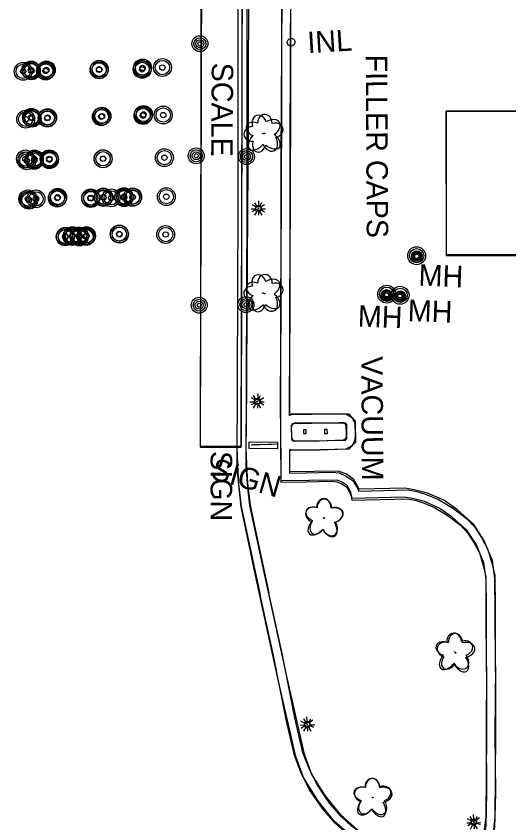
# Model space of a CAD drawing. Extents: x 588843 to 2552415, y 180129 to 269402.
# Drawn here: x 594348.8 to 594486.6, y 184634.7 to 184860.3 of the extents above; entities that cross this region are included whole.
import ezdxf

# ---------------------------------------------------------------- set-up
doc = ezdxf.new("R2010")
doc.units = 0
for name, color, linetype in [('Default', 7, 'Continuous'), ('E_AREA', 7, 'Continuous'), ('E_BLD_Dash', 7, 'Continuous'), ('E_BLD_HvyDash', 7, 'Continuous'), ('E_BLD_Text', 7, 'Continuous'), ('E_BLD_Vacuum', 7, 'Continuous'), ('E_DRN', 7, 'Continuous'), ('E_DRN_Text', 7, 'Continuous'), ('E_DWY', 7, 'Continuous'), ('E_LAND_Vegetation', 7, 'Continuous'), ('E_LTG', 7, 'Continuous'), ('E_MISCPROP', 7, 'Continuous'), ('E_MISCPROP_Text', 7, 'Continuous'), ('E_SGN', 7, 'Continuous'), ('E_SGN_Text', 7, 'Continuous'), ('E_UTL_MH', 7, 'Continuous'), ('E_UTL_MH_Text', 7, 'Continuous')]:
    doc.layers.add(name, color=color, linetype=linetype)

# ---------------------------------------------------------------- blocks, each defined once
blk = doc.blocks.new('SIGN')
at = {"layer": 'Default'}
blk.add_text('SIGN', height=12, dxfattribs=at).set_placement((-18.55, -6))
blk = doc.blocks.new('SCAL')
at = {"layer": 'Default'}
blk.add_text('SCALE', height=12, dxfattribs=at).set_placement((-23.24, -6))
blk = doc.blocks.new('POLE')
at = {"layer": 'Default'}
for radius in [4.46, 3.35, 2.23, 1.12]:
    blk.add_circle((0, 0), radius, dxfattribs=at)
blk = doc.blocks.new('LPOL')
at = {"layer": 'Default'}
for p, q in [((-4, 0), (-1.5, 0)), ((-0.75, 1.3), (-2, 3.46)), ((0.75, 1.3), (2, 3.46)), ((1.5, 0), (4, 0)), ((-2, -3.46), (-0.75, -1.3)), ((2, -3.46), (0.75, -1.3))]:
    blk.add_line(p, q, dxfattribs=at)
for radius in [1.5, 1.5, 1.5, 0.125]:
    blk.add_circle((0, 0), radius, dxfattribs=at)
blk = doc.blocks.new('DTRE')
at = {"layer": 'Default'}
blk.add_circle((-0.18, 0), 0.183, dxfattribs=at)
for centre, major_axis, ratio in [((-1.87, 5.32), (1.36, -4.98), 0.782863), ((4.06, 2.74), (-5.27, -2.93), 0.691916), ((-5.87, 0.15), (4.93, -0.12), 0.832022), ((-2.49, -5.24), (1.8, 4.86), 0.716896), ((3.54, -3.71), (-5.01, 4.58), 0.560249)]:
    blk.add_ellipse(centre, major_axis=major_axis, ratio=ratio, start_param=1.570796, end_param=4.712389, dxfattribs=at)
blk = doc.blocks.new('FILO')
at = {"layer": 'E_MISCPROP'}
for radius in [5, 4, 1.5]:
    blk.add_circle((0, 0), radius, dxfattribs=at)
blk = doc.blocks.new('VACO')
at = {"layer": 'E_BLD_Vacuum'}
blk.add_lwpolyline([(0, 1.5), (0, 0), (2.2, 0), (2.2, 1.5), (0, 1.5)], close=True, dxfattribs=at)
blk = doc.blocks.new('VAC')
at = {"layer": 'E_BLD_Text'}
blk.add_text('VACUUM', height=12, dxfattribs=at).set_placement((-33.33, -6))
blk = doc.blocks.new('FILT_4')
at = {"layer": 'E_MISCPROP_Text'}
blk.add_text('FILLER CAPS', height=12, dxfattribs=at).set_placement((10, -6))
blk = doc.blocks.new('LPOL_4')
at = {"layer": 'E_LTG'}
for p, q in [((-13.1, 0), (-4.9, 0)), ((-2.5, 4.3), (-6.6, 11.4)), ((2.5, 4.3), (6.6, 11.4)), ((4.9, 0), (13.1, 0)), ((-6.6, -11.4), (-2.5, -4.3)), ((6.6, -11.4), (2.5, -4.3))]:
    blk.add_line(p, q, dxfattribs=at)
for radius in [4.92, 4.92, 4.92, 0.41]:
    blk.add_circle((0, 0), radius, dxfattribs=at)
blk = doc.blocks.new('FILO_1')
at = {"layer": 'E_MISCPROP'}
for radius in [16.4, 13.1, 4.92]:
    blk.add_circle((0, 0), radius, dxfattribs=at)
blk = doc.blocks.new('INLT_32_2')
at = {"layer": 'E_DRN_Text'}
blk.add_text('INL', height=39.37, dxfattribs=at).set_placement((-36.2, -19.7))
blk = doc.blocks.new('MHO_3')
at = {"layer": 'E_UTL_MH'}
for centre, radius in [((0.3, -0.4), 9.84), ((0.3, -0.4), 7.98), ((0.2, -0.5), 6.35), ((0.1, -0.5), 3.97)]:
    blk.add_circle(centre, radius, dxfattribs=at)
blk = doc.blocks.new('MHT_3')
at = {"layer": 'E_UTL_MH_Text'}
blk.add_text('MH', height=39.37, dxfattribs=at).set_placement((-32.2, -19.7))
blk = doc.blocks.new('DTRE_4')
at = {"layer": 'E_LAND_Vegetation'}
blk.add_circle((-0.6, 0), 0.601, dxfattribs=at)
for centre, major_axis, ratio in [((-6.1, 17.5), (4.5, -16.3), 0.782863), ((13.3, 9), (-17.3, -9.6), 0.691916), ((-19.3, 0.5), (16.2, -0.4), 0.832022), ((-8.2, -17.2), (5.9, 15.9), 0.716896), ((11.6, -12.2), (-16.4, 15), 0.560249)]:
    blk.add_ellipse(centre, major_axis=major_axis, ratio=ratio, start_param=1.570796, end_param=4.712389, dxfattribs=at)
blk = doc.blocks.new('SIGN_3')
at = {"layer": 'E_SGN'}
blk.add_text('SIGN', height=39.37, dxfattribs=at).set_placement((-56.1, -19.7))

msp = doc.modelspace()

# ---------------------------------------------------------------- linework, layer by layer
at = {"layer": 'E_AREA'}
msp.add_lwpolyline([(594414.04, 184741.25), (594421.91, 184741.15), (594421.89, 184739.31), (594414.02, 184739.41)], close=True, dxfattribs=at)
at = {"layer": 'E_BLD_Dash'}
msp.add_lwpolyline([(594400.82, 184942.87), (594400.29, 184739.8), (594411.76, 184739.77), (594412.3, 184942.83)], close=True, dxfattribs=at)
at = {"layer": 'E_BLD_HvyDash'}
for points in [[(594412.17, 184942.93), (594411.81, 184740.07), (594400.36, 184739.94), (594400.8, 184943.06), (594412.17, 184942.93)], [(594469.12, 184833.63), (594539.86, 184833.96), (594539.49, 184793.32), (594469.23, 184793.25)], [(594469.2, 184793.54), (594469.17, 184833.83), (594540.12, 184833.88), (594540.15, 184793.6), (594469.2, 184793.54)]]:
    msp.add_lwpolyline(points, close=True, dxfattribs=at)
at = {"layer": 'E_DRN'}
msp.add_ellipse((594425.73, 184853.02), major_axis=(0.31, 1.04), ratio=0.999083, dxfattribs=at)
at = {"layer": 'E_DWY'}
for points in [[(594421.96, 184675.59), (594415.82, 184703.87), (594411.73, 184723.08), (594411.26, 184727.36), (594410.68, 184734.11), (594410.96, 184807.45), (594410.92, 184870.64), (594411.16, 184901.91), (594411.17, 184939.88)], [(594424.41, 184676.12), (594418.27, 184704.4), (594414.2, 184723.48), (594413.75, 184727.6), (594413.18, 184734.21), (594413.46, 184807.45), (594413.42, 184870.63), (594413.66, 184901.89), (594413.67, 184939.88)], [(594447.77, 184915.17), (594448.18, 184897.65), (594448.19, 184895.9), (594447.53, 184894.66), (594446.24, 184893.39), (594445.15, 184892.78), (594441.01, 184892.63), (594423.19, 184892.62), (594423.1, 184870.83), (594423.02, 184855.19), (594423.02, 184838.7), (594422.95, 184807.7), (594422.8, 184779.99), (594422.79, 184749.18), (594422.83, 184730.02), (594429.93, 184730.14)], [(594450.27, 184915.23), (594450.68, 184897.69), (594450.7, 184895.29), (594449.56, 184893.15), (594447.76, 184891.37), (594445.84, 184890.3), (594441.06, 184890.13), (594425.68, 184890.12), (594425.6, 184870.82), (594425.52, 184855.18), (594425.52, 184838.7), (594425.45, 184807.69), (594425.3, 184779.99), (594425.29, 184749.18), (594425.29, 184748.72)], [(594425.33, 184748.66), (594425.31, 184753.72), (594425.45, 184777.31), (594425.48, 184799.41), (594425.47, 184820.54), (594425.6, 184851.34), (594425.7, 184865.36), (594425.84, 184889.86), (594440.33, 184889.96), (594445.07, 184890.02), (594447.12, 184890.68), (594448.91, 184892.09), (594450.28, 184894.21), (594450.81, 184896.05), (594450.4, 184915.27)], [(594413.61, 184904.03), (594413.83, 184876.2), (594413.68, 184831.02), (594413.36, 184779.01), (594413.27, 184758.12), (594413.16, 184745.67)], [(594480.38, 184678.45), (594480.29, 184693.97), (594480.25, 184702.88), (594479.6, 184707.44), (594477.45, 184712.65), (594474.89, 184716.54), (594470.69, 184720.3), (594467.18, 184722.78), (594463.03, 184724.57), (594459.67, 184725.43), (594457.35, 184725.79), (594442.77, 184725.45), (594442.43, 184727.18), (594441.4, 184729.04), (594440.03, 184730.04), (594438.57, 184730.59), (594422.92, 184730.39), (594422.81, 184753.72), (594422.95, 184777.32), (594422.98, 184799.41), (594422.97, 184820.54), (594423.1, 184851.35), (594423.2, 184865.37)], [(594425.29, 184748.72), (594425.71, 184748.95), (594428.09, 184749), (594431.39, 184749)], [(594425.33, 184748.66), (594426.05, 184749.18), (594430.53, 184749.13)], [(594430.53, 184749.13), (594441.92, 184749.14), (594443.68, 184747.16), (594443.72, 184741.05), (594441.92, 184739.2), (594425.72, 184738.9), (594425.38, 184739.21)], [(594431.39, 184749), (594439.19, 184749.23), (594441.02, 184749.14), (594442.61, 184748.22), (594443.51, 184746.61), (594443.62, 184742.75), (594443.43, 184741.59), (594442.76, 184740.19), (594441.05, 184739.24), (594433.7, 184738.99)], [(594413.16, 184745.76), (594413.06, 184739.72), (594413.22, 184735), (594413.55, 184729.65), (594414.24, 184723.57), (594416.79, 184711.65), (594419.51, 184699.02)], [(594433.61, 184741.49), (594426.99, 184741.49), (594426.31, 184741.49), (594426.03, 184741.7), (594425.87, 184745.13), (594425.92, 184745.79), (594425.99, 184746.04), (594426.06, 184746.29), (594426.38, 184746.47), (594428.15, 184746.5), (594431.47, 184746.5)], [(594430.51, 184746.63), (594440.81, 184746.62), (594441.19, 184746.2), (594441.21, 184742.06), (594440.85, 184741.68), (594426.66, 184741.42), (594425.97, 184742.03), (594425.89, 184745.98), (594426.85, 184746.67), (594430.51, 184746.63)], [(594431.46, 184746.5), (594439.16, 184746.73), (594440.3, 184746.67), (594440.76, 184746.41), (594441.03, 184745.92), (594441.12, 184742.93), (594441.02, 184742.35), (594440.85, 184741.99), (594440.37, 184741.72), (594433.61, 184741.49)], [(594410.57, 184740.06), (594410.56, 184739.73), (594410.72, 184734.88), (594411.06, 184729.43), (594411.77, 184723.16), (594414.34, 184711.12), (594417.07, 184698.49)], [(594433.61, 184738.99), (594427, 184738.99), (594425.47, 184738.97), (594425.31, 184739.1)], [(594425.31, 184739.1), (594425.33, 184732.56), (594429.89, 184732.64)], [(594482.88, 184678.47), (594482.79, 184693.99), (594482.75, 184703.06), (594482.03, 184708.1), (594479.67, 184713.83), (594476.79, 184718.19), (594472.24, 184722.26), (594468.4, 184724.97), (594463.84, 184726.94), (594460.17, 184727.88), (594457.52, 184728.3), (594444.82, 184728), (594444.81, 184728.05), (594443.31, 184730.74), (594441.24, 184732.25), (594439.02, 184733.09), (594425.41, 184732.92), (594425.38, 184739.21)], [(594429.89, 184732.64), (594437.11, 184732.76), (594439.18, 184732.59), (594440.91, 184731.79), (594443.01, 184730.46), (594444.33, 184728.29), (594444.65, 184727.5), (594458.45, 184727.82), (594460.86, 184727.37), (594463.28, 184726.67), (594466.98, 184725.17), (594471.11, 184722.67), (594474.83, 184719.84), (594477.08, 184717.42), (594479.04, 184714.38), (594480.73, 184711.16), (594481.84, 184707.32), (594482.71, 184704), (594482.83, 184694.45)], [(594429.93, 184730.14), (594437.03, 184730.25), (594438.53, 184730.13), (594439.71, 184729.59), (594441.18, 184728.66), (594442.09, 184727.17), (594442.51, 184726.13), (594442.68, 184724.95), (594458.25, 184725.31), (594460.29, 184724.93), (594462.46, 184724.31), (594465.86, 184722.93), (594469.7, 184720.6), (594473.14, 184717.97), (594475.1, 184715.88), (594476.87, 184713.12), (594478.4, 184710.22), (594479.43, 184706.65), (594480.21, 184703.67), (594480.33, 184694.42)], [(594420.77, 184681.55), (594417.07, 184698.49)], [(594423.21, 184682.07), (594419.51, 184699.02)], [(594482.83, 184694.42), (594482.92, 184659.67), (594482.71, 184636.24), (594482.31, 184632.89), (594481.78, 184630.62), (594480.58, 184627.84), (594478.42, 184625.82), (594475.9, 184623.95), (594473.46, 184623.13), (594469.07, 184622.62), (594458.61, 184624.11), (594452.88, 184625.43), (594448.95, 184627.22), (594443.75, 184630.02), (594437.8, 184635.22), (594433.19, 184640.96), (594429.19, 184647.4), (594427.04, 184653.28), (594421.97, 184675.56)], [(594480.33, 184694.42), (594480.42, 184659.68), (594480.21, 184636.4), (594479.84, 184633.33), (594479.39, 184631.41), (594478.49, 184629.31), (594476.81, 184627.74), (594474.73, 184626.19), (594472.92, 184625.58), (594469.1, 184625.14), (594459.07, 184626.57), (594453.69, 184627.81), (594450.06, 184629.46), (594445.18, 184632.08), (594439.62, 184636.95), (594435.24, 184642.4), (594431.45, 184648.5), (594429.44, 184654), (594424.41, 184676.12)], [(594482.88, 184678.47), (594482.74, 184659.75), (594482.91, 184643.05), (594482.66, 184633.41), (594481.76, 184629.69), (594479.69, 184626.74), (594476.79, 184624.45), (594474.31, 184623.27), (594471.26, 184622.72), (594468.48, 184622.7), (594461.92, 184623.38), (594457.38, 184624.13), (594453.05, 184625.41), (594448.66, 184627.01), (594444.67, 184629.31), (594440.93, 184632.02), (594438.05, 184634.69), (594434.53, 184638.75), (594430.91, 184644.03), (594428.65, 184648.48), (594426.64, 184653.58), (594424.31, 184663.61), (594420.77, 184681.55)], [(594480.38, 184678.45), (594480.24, 184659.73), (594480.41, 184643.07), (594480.16, 184633.74), (594479.44, 184630.73), (594477.86, 184628.48), (594475.46, 184626.59), (594473.53, 184625.67), (594471.03, 184625.21), (594468.6, 184625.2), (594462.25, 184625.86), (594457.94, 184626.57), (594453.83, 184627.78), (594449.72, 184629.28), (594446.03, 184631.41), (594442.52, 184633.96), (594439.84, 184636.43), (594436.51, 184640.28), (594433.07, 184645.31), (594430.94, 184649.51), (594429.04, 184654.33), (594426.75, 184664.14), (594423.21, 184682.07)]]:
    msp.add_lwpolyline(points, dxfattribs=at)
at = {"layer": 'E_SGN'}
msp.add_line((594421.87, 184740.65), (594414.62, 184740.37), dxfattribs=at)
msp.add_lwpolyline([(594414.75, 184740.55), (594420.13, 184740.61)], dxfattribs=at)

# ---------------------------------------------------------------- block references
at = {"layer": 'E_BLD_Text'}
for name, p, xscale, yscale, rotation in [('SCAL', (594406.47, 184835.67), 0.4999999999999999, 0.49999999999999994, -90.39935623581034), ('VAC', (594448.43, 184748.55), 0.49999999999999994, 0.4999999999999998, -89.6710262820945)]:
    msp.add_blockref(name, p, dxfattribs=dict(at, xscale=xscale, yscale=yscale, rotation=rotation))
at = {"layer": 'E_BLD_Vacuum', "xscale": 0.49999999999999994, "yscale": 0.4999999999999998, "rotation": -89.6710262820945}
for p in [(594429.23, 184744.67), (594435.11, 184744.74)]:
    msp.add_blockref('VACO', p, dxfattribs=at)
at = {"layer": 'E_DRN_Text', "xscale": 0.15240030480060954, "yscale": 0.15240030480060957, "rotation": 3.4338469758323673}
msp.add_blockref('INLT_32_2', (594435.79, 184853.25), dxfattribs=at)
at = {"layer": 'E_LAND_Vegetation'}
for name, p, xscale, yscale, rotation in [('DTRE_4', (594417.96, 184827.49), 0.15240030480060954, 0.15240030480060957, 3.4338469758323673), ('DTRE', (594418.29, 184827.42), 0.4999999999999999, 0.49999999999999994, -90.39935623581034), ('DTRE_4', (594417.89, 184782.87), 0.15240030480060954, 0.15240030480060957, 3.4338469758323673), ('DTRE', (594418.3, 184782.66), 0.4999999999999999, 0.49999999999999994, -90.39935623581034), ('DTRE_4', (594435.02, 184720.04), 0.1524003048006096, 0.1524003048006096, -15.969778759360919), ('DTRE', (594434.97, 184719.84), 0.49999999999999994, 0.4999999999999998, -89.6710262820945), ('DTRE_4', (594471.83, 184682.27), 0.1524003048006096, 0.1524003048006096, -15.969778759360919), ('DTRE', (594471.47, 184682.43), 0.49999999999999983, 0.4999999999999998, -85.64095942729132), ('DTRE_4', (594448.67, 184641.79), 0.1524003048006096, 0.1524003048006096, -15.969778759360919), ('DTRE', (594448.56, 184641.77), 0.49999999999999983, 0.4999999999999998, -85.64095942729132)]:
    msp.add_blockref(name, p, dxfattribs=dict(at, xscale=xscale, yscale=yscale, rotation=rotation))
at = {"layer": 'E_LTG'}
for name, p, xscale, yscale, rotation in [('LPOL_4', (594416.6, 184806.42), 0.15240030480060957, 0.15240030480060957, 0.8014450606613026), ('LPOL', (594416.6, 184806.63), 0.4999999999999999, 0.49999999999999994, -90.39935623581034), ('LPOL_4', (594416.22, 184752.47), 0.15240030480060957, 0.15240030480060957, 0.8014450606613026), ('LPOL', (594416.39, 184752.68), 0.4999999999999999, 0.49999999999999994, -90.39935623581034), ('LPOL_4', (594430.29, 184662.13), 0.15240030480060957, 0.15240030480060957, 0.8014450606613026), ('LPOL', (594430.2, 184662.38), 0.49999999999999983, 0.4999999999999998, -85.64095942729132), ('LPOL_4', (594476.84, 184634.78), 0.15240030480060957, 0.15240030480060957, 0.8014450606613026), ('LPOL', (594476.8, 184635.12), 0.49999999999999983, 0.4999999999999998, -85.64095942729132)]:
    msp.add_blockref(name, p, dxfattribs=dict(at, xscale=xscale, yscale=yscale, rotation=rotation))
at = {"layer": 'E_MISCPROP'}
for name, p, xscale, yscale, rotation in [('POLE', (594400.23, 184852.6), 0.4999999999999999, 0.49999999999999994, -90.39935623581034), ('FILO', (594384.19, 184845.81), 0.4999999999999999, 0.49999999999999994, -90.39935623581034), ('FILO', (594389.75, 184845.93), 0.4999999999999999, 0.49999999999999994, -90.39935623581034), ('FILO_1', (594350.81, 184844.86), 0.15240030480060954, 0.15240030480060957, 3.4338469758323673), ('FILO', (594352.96, 184845.22), 0.4999999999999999, 0.49999999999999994, -90.39935623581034), ('FILO_1', (594353.09, 184845.02), 0.15240030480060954, 0.15240030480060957, 3.4338469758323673), ('FILO_1', (594357.06, 184844.97), 0.15240030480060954, 0.15240030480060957, 3.4338469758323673), ('FILO', (594357.29, 184845.26), 0.4999999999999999, 0.49999999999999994, -90.39935623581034), ('FILO_1', (594372.02, 184845.28), 0.15240030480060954, 0.15240030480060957, 3.4338469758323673), ('FILO', (594372.1, 184845.45), 0.4999999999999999, 0.49999999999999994, -90.39935623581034), ('FILO_1', (594384.08, 184845.41), 0.15240030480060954, 0.15240030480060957, 3.4338469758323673), ('FILO_1', (594372.66, 184832.19), 0.15240030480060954, 0.15240030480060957, 3.4338469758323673), ('FILO', (594372.84, 184832.34), 0.4999999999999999, 0.49999999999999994, -90.39935623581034), ('FILO_1', (594384.31, 184832.51), 0.15240030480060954, 0.15240030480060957, 3.4338469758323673), ('FILO', (594384.45, 184832.81), 0.4999999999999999, 0.49999999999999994, -90.39935623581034), ('FILO', (594389.97, 184832.65), 0.4999999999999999, 0.49999999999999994, -90.39935623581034), ('FILO_1', (594351.51, 184831.48), 0.15240030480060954, 0.15240030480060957, 3.4338469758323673), ('FILO', (594353.12, 184831.99), 0.4999999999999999, 0.49999999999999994, -90.39935623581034), ('FILO_1', (594353.29, 184831.79), 0.15240030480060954, 0.15240030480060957, 3.4338469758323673), ('FILO_1', (594357.54, 184831.78), 0.15240030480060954, 0.15240030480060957, 3.4338469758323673), ('FILO', (594357.64, 184831.92), 0.4999999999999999, 0.49999999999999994, -90.39935623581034), ('POLE', (594399.19, 184821.24), 0.4999999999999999, 0.49999999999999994, -90.39935623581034), ('FILO', (594351.44, 184820.38), 0.4999999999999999, 0.49999999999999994, -90.39935623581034), ('FILO_1', (594351.83, 184819.84), 0.15240030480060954, 0.15240030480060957, 3.4338469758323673), ('FILO_1', (594353.9, 184819.99), 0.15240030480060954, 0.15240030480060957, 3.4338469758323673), ('FILO', (594353.94, 184820.37), 0.4999999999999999, 0.49999999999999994, -90.39935623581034), ('FILO_1', (594358.15, 184820.19), 0.15240030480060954, 0.15240030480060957, 3.4338469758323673), ('FILO', (594358.09, 184820.41), 0.4999999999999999, 0.49999999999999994, -90.39935623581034), ('FILO_1', (594373.15, 184820.43), 0.15240030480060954, 0.15240030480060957, 3.4338469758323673), ('FILO', (594373.16, 184820.41), 0.4999999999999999, 0.49999999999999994, -90.39935623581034), ('FILO', (594390.3, 184820.72), 0.4999999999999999, 0.49999999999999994, -90.39935623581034), ('POLE', (594413.26, 184821.02), 0.4999999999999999, 0.49999999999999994, -90.39935623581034), ('FILO', (594360.46, 184809.64), 0.4999999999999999, 0.49999999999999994, -90.39935623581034), ('FILO_1', (594373.22, 184809.59), 0.15240030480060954, 0.15240030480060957, 3.4338469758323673), ('FILO', (594373.25, 184809.72), 0.4999999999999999, 0.49999999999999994, -90.39935623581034), ('FILO_1', (594375.43, 184809.5), 0.15240030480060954, 0.15240030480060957, 3.4338469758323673), ('FILO_1', (594379.02, 184809.55), 0.15240030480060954, 0.15240030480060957, 3.4338469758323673), ('FILO', (594378.98, 184809.84), 0.4999999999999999, 0.49999999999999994, -90.39935623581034), ('FILO_1', (594381.34, 184809.63), 0.15240030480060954, 0.15240030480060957, 3.4338469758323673), ('FILO', (594381.44, 184809.75), 0.4999999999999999, 0.49999999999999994, -90.39935623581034), ('FILO', (594390.84, 184809.82), 0.4999999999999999, 0.49999999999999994, -90.39935623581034), ('FILO', (594352.11, 184809.19), 0.4999999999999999, 0.49999999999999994, -90.39935623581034), ('FILO_1', (594352.4, 184808.86), 0.15240030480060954, 0.15240030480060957, 3.4338469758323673), ('FILO', (594354.39, 184809.21), 0.4999999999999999, 0.49999999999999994, -90.39935623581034), ('FILO_1', (594360.34, 184809.43), 0.15240030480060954, 0.15240030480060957, 3.4338469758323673), ('FILO_1', (594369.7, 184809.32), 0.15240030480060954, 0.15240030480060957, 3.4338469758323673), ('FILO', (594369.68, 184809.49), 0.4999999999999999, 0.49999999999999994, -90.39935623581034), ('FILO_1', (594362.57, 184798.58), 0.15240030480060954, 0.15240030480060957, 3.4338469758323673), ('FILO', (594362.6, 184798.73), 0.4999999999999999, 0.49999999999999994, -90.39935623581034), ('FILO_1', (594364.5, 184798.71), 0.15240030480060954, 0.15240030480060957, 3.4338469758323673), ('FILO', (594364.65, 184798.91), 0.4999999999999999, 0.49999999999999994, -90.39935623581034), ('FILO_1', (594366.48, 184798.55), 0.15240030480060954, 0.15240030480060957, 3.4338469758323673), ('FILO', (594366.52, 184798.88), 0.4999999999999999, 0.49999999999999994, -90.39935623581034), ('FILO_1', (594368.35, 184798.69), 0.15240030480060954, 0.15240030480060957, 3.4338469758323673), ('FILO', (594368.51, 184798.9), 0.4999999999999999, 0.49999999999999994, -90.39935623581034), ('FILO_1', (594377.72, 184799.32), 0.15240030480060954, 0.15240030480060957, 3.4338469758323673), ('FILO', (594377.66, 184799.39), 0.4999999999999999, 0.49999999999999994, -90.39935623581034), ('FILO', (594390.65, 184799.24), 0.4999999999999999, 0.49999999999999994, -90.39935623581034), ('FILO', (594460.84, 184793.31), 0.49999999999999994, 0.4999999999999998, -89.6710262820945), ('FILO', (594452.48, 184782.56), 0.49999999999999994, 0.4999999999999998, -89.6710262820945), ('FILO', (594456.21, 184782.26), 0.49999999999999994, 0.4999999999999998, -89.6710262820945), ('POLE', (594400.03, 184779.48), 0.4999999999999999, 0.49999999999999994, -90.39935623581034), ('POLE', (594413.08, 184779.64), 0.4999999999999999, 0.49999999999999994, -90.39935623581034)]:
    msp.add_blockref(name, p, dxfattribs=dict(at, xscale=xscale, yscale=yscale, rotation=rotation))
at = {"layer": 'E_MISCPROP_Text', "xscale": 0.49999999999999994, "yscale": 0.4999999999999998, "rotation": -89.6710262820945}
msp.add_blockref('FILT_4', (594449.57, 184854.54), dxfattribs=at)
at = {"layer": 'E_SGN_Text'}
for name, p, xscale, yscale, rotation in [('SIGN', (594406.23, 184729.43), 0.49999999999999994, 0.5, -90.03098035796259), ('SIGN_3', (594412, 184731.59), 0.1524003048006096, 0.1524003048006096, -15.969778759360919)]:
    msp.add_blockref(name, p, dxfattribs=dict(at, xscale=xscale, yscale=yscale, rotation=rotation))
at = {"layer": 'E_UTL_MH'}
for p, xscale, yscale, rotation in [((594460.85, 184793.23), 0.15240030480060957, 0.15240030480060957, -2.198250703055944), ((594452.41, 184782.4), 0.15240030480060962, 0.1524003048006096, -2.163912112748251), ((594456.17, 184782.07), 0.1524003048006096, 0.15240030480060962, -2.071693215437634)]:
    msp.add_blockref('MHO_3', p, dxfattribs=dict(at, xscale=xscale, yscale=yscale, rotation=rotation))
at = {"layer": 'E_UTL_MH_Text'}
for p, xscale, yscale, rotation in [((594466.31, 184787.75), 0.15240030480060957, 0.15240030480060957, -2.198250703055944), ((594463.28, 184777.87), 0.1524003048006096, 0.15240030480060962, -2.071693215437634), ((594449.32, 184776.33), 0.15240030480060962, 0.1524003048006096, -2.163912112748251)]:
    msp.add_blockref('MHT_3', p, dxfattribs=dict(at, xscale=xscale, yscale=yscale, rotation=rotation))

doc.saveas('drawing.dxf')
